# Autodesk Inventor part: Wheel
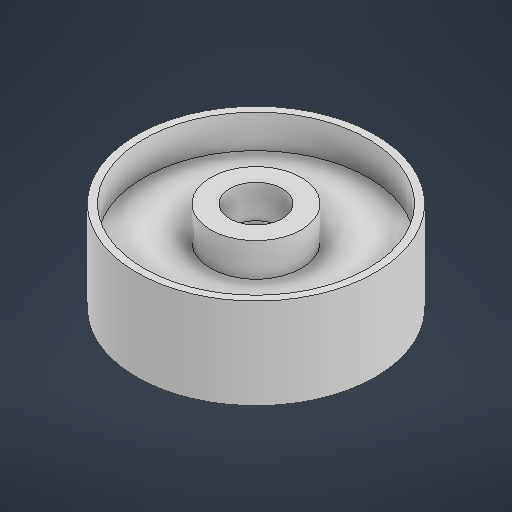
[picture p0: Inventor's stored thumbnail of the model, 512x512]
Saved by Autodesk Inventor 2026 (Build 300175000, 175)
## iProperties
Created: 2025-05
Part Number: Wheel
Material: Generic
Document SubType Name: Modeling
Designer: Ritul Kumari
Density: 1 g/cm^3
Appearance: Default
Author: Ritul Kumari
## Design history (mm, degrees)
node "3D Sketch1"
sketch "Sketch1"
  geometry: L1 (0, 0)-(279.4, 0); L2 (279.4, 0)-(279.4, 355.6); L3 (279.4, 355.6)-(482.6, 355.6); L4 (482.6, 355.6)-(482.6, 0); L5 (482.6, 0)-(1193.8, 0); L6 (1193.8, 0)-(1193.8, 355.6); L7 (1193.8, 355.6)-(1270, 355.6); L8 (1270, 355.6)-(1270, 0); L9 (1270, 0)-(1270, -609.6); L10 (1270, 0)-(1879.6, 0); L11 (1270, -609.6)-(1193.8, -609.6); L12 (1193.8, -609.6)-(1193.8, -254); L13 (1193.8, -254)-(482.6, -254); L14 (482.6, -254)-(482.6, -609.6); L15 (482.6, -609.6)-(279.4, -609.6); L16 (279.4, -609.6)-(279.4, -254); L17 (279.4, -254)-(0, -254); L18 (0, -254)-(0, 0)
  constraints: 36 end point, 9 perpendicular, 6 horizontal, 3 vertical, 1 point on line
  dimensions: "d0" = 279.4 distance of L1.start L1.end; "d1" = 355.6 distance of L1.end L2.end; "d2" = 203.2 distance of L2.end L3.end; "d3" = 711.2 distance of L4.end L5.end; "d4" = 355.6 distance of L5.end L6.end; "d5" = 76.2 distance of L6.end L7.end; "d6" = 609.6 distance of L8.end L9.end; "d7" = 90 deg angle of L9 L10 (derived); "d8" = 76.2 distance of L9.end L11.end; "d9" = 355.6 distance of L11.end L12.end; "d10" = 355.6 distance of L13.end L14.end; "d11" = 203.2 distance of L14.end L15.end; "d12" = 355.6 distance of L15.end L16.end
revolve "Revolution1" sketch "Sketch1" stored, may be unused: angle "d13" = 90 deg
node "Wheel"
